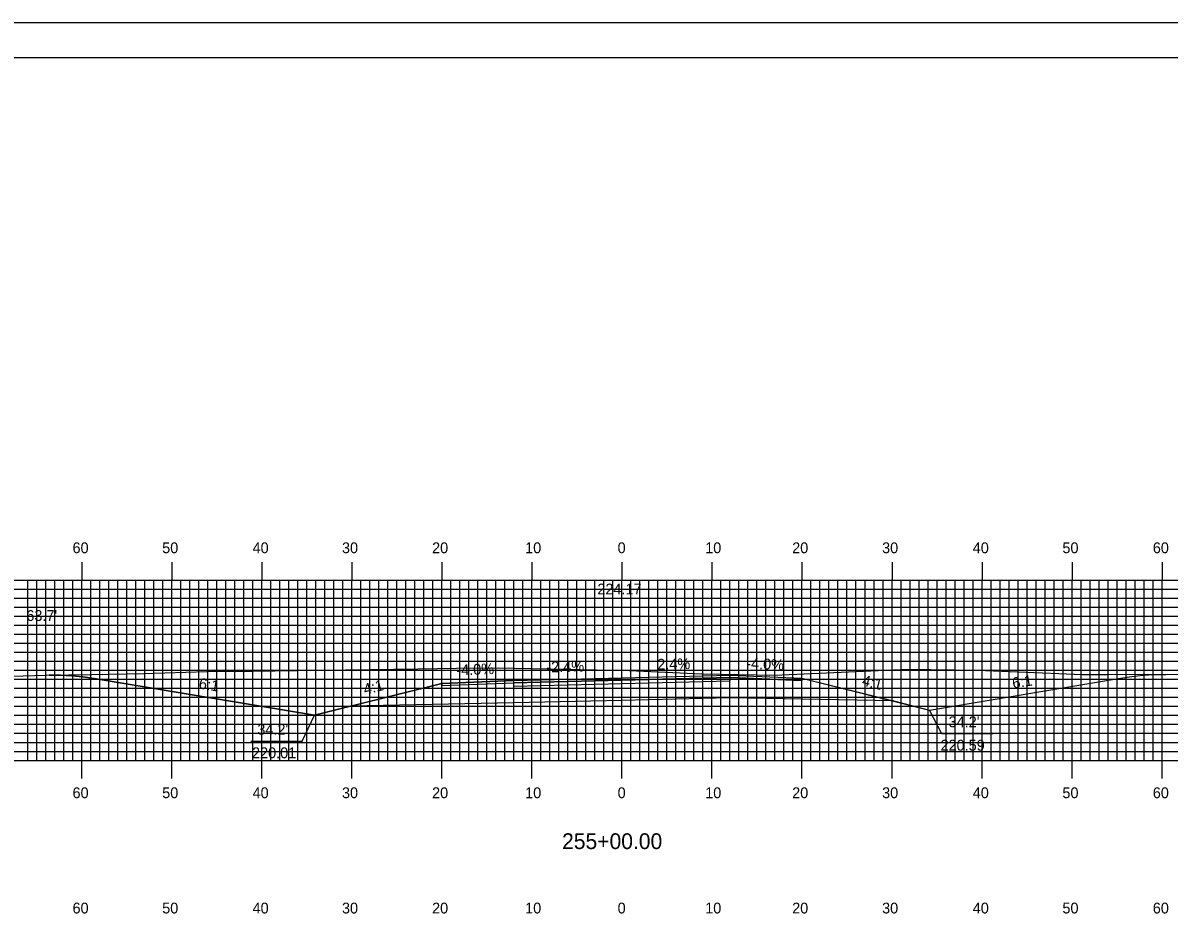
# Model space of a CAD drawing. Extents: x 1804684 to 1805027, y 442591 to 442811.
# Drawn here: x 1804783.1 to 1804910.5, y 442711.2 to 442810.5 of the extents above; entities that cross this region are included whole.
import ezdxf

# ---------------------------------------------------------------- set-up
doc = ezdxf.new("R2010")
doc.units = 0
for name, color, linetype in [('ANNOTATION', 7, 'Continuous'), ('BORDER', 7, 'Continuous'), ('D_Roadway_Centerline', 7, 'Continuous'), ('D_Roadway_Centerline_Text', 7, 'Continuous'), ('D_Roadway_Edge_Shoulder', 7, 'Continuous'), ('D_Roadway_Edge_TW', 7, 'Continuous'), ('D_Roadway_Pavement', 7, 'Continuous'), ('D_Roadway_SlopeLines', 7, 'Continuous'), ('D_Roadway_SubGrade', 7, 'Continuous'), ('D_Text_Standard', 7, 'Continuous'), ('H_V ANNOTATION', 7, 'Continuous'), ('MAJOR', 7, 'Continuous'), ('MINOR', 7, 'Continuous'), ('PLOT BOUNDARY', 7, 'Continuous'), ('S_Roadway_Centerline', 7, 'Continuous')]:
    doc.layers.add(name, color=color, linetype=linetype)

msp = doc.modelspace()

# ---------------------------------------------------------------- linework, layer by layer
at = {"layer": 'ANNOTATION'}
for points in [[(1804808.45, 442730.79), (1804814.14, 442730.79), (1804815.51, 442733.68)], [(1804890.92, 442731.62), (1804885.23, 442731.62), (1804883.85, 442734.26)]]:
    msp.add_lwpolyline(points, dxfattribs=at)
at = {"layer": 'BORDER'}
msp.add_lwpolyline([(1804700.08, 442596.67), (1805020.08, 442596.67), (1805020.08, 442806.67), (1804700.08, 442806.67)], close=True, dxfattribs=at)
at = {"layer": 'D_Roadway_Centerline'}
msp.add_lwpolyline([(1804786.06, 442738.13), (1804787.31, 442738.12), (1804788.56, 442738.06), (1804789.81, 442737.93), (1804791.06, 442737.75), (1804815.51, 442733.68), (1804819.51, 442734.68), (1804829.68, 442737.22), (1804837.68, 442737.54), (1804849.68, 442737.83), (1804861.68, 442738.12), (1804869.68, 442737.8), (1804879.85, 442735.26), (1804883.85, 442734.26), (1804905.08, 442737.79), (1804906.33, 442737.98), (1804907.58, 442738.11), (1804908.83, 442738.19), (1804910.08, 442738.22)], dxfattribs=at)
at = {"layer": 'D_Roadway_Edge_Shoulder'}
for points in [[(1804837.68, 442737.54), (1804829.68, 442737.22), (1804829.68, 442736.97), (1804837.68, 442737.29)], [(1804861.68, 442738.12), (1804869.68, 442737.8), (1804869.68, 442737.55), (1804861.68, 442737.87)]]:
    msp.add_lwpolyline(points, close=True, dxfattribs=at)
at = {"layer": 'D_Roadway_Edge_TW'}
msp.add_lwpolyline([(1804837.68, 442737.29), (1804837.68, 442737.54), (1804849.68, 442737.83), (1804861.68, 442738.12), (1804861.68, 442737.87), (1804849.68, 442737.58)], close=True, dxfattribs=at)
at = {"layer": 'D_Roadway_Pavement'}
msp.add_lwpolyline([(1804837.68, 442736.88), (1804837.68, 442737.29), (1804849.68, 442737.58), (1804861.68, 442737.87), (1804861.68, 442737.45), (1804849.68, 442737.16)], close=True, dxfattribs=at)
at = {"layer": 'D_Roadway_SlopeLines'}
for points in [[(1804815.51, 442733.68), (1804791.06, 442737.75), (1804789.81, 442737.93), (1804788.56, 442738.06), (1804787.31, 442738.12), (1804786.06, 442738.13)], [(1804829.68, 442737.22), (1804815.51, 442733.68)], [(1804869.68, 442737.8), (1804883.85, 442734.26)], [(1804883.85, 442734.26), (1804905.08, 442737.79), (1804906.33, 442737.98), (1804907.58, 442738.11), (1804908.83, 442738.19), (1804910.08, 442738.22)]]:
    msp.add_lwpolyline(points, dxfattribs=at)
at = {"layer": 'D_Roadway_SubGrade'}
msp.add_lwpolyline([(1804837.68, 442735.04), (1804819.51, 442734.68), (1804829.68, 442737.22), (1804829.68, 442736.97), (1804837.68, 442737.29), (1804849.68, 442737.58), (1804861.68, 442737.87), (1804869.68, 442737.55), (1804869.68, 442737.8), (1804879.85, 442735.26), (1804861.68, 442735.62), (1804849.68, 442735.33)], close=True, dxfattribs=at)
at = {"layer": 'MAJOR'}
for p, q in [((1804789.68, 442750.67), (1804789.68, 442748.67)), ((1804799.68, 442750.67), (1804799.68, 442748.67)), ((1804809.68, 442750.67), (1804809.68, 442748.67)), ((1804819.68, 442750.67), (1804819.68, 442748.67)), ((1804829.68, 442750.67), (1804829.68, 442748.67)), ((1804839.68, 442750.67), (1804839.68, 442748.67)), ((1804849.68, 442750.67), (1804849.68, 442748.67)), ((1804859.68, 442750.67), (1804859.68, 442748.67)), ((1804869.68, 442750.67), (1804869.68, 442748.67)), ((1804879.68, 442750.67), (1804879.68, 442748.67)), ((1804889.68, 442750.67), (1804889.68, 442748.67)), ((1804899.68, 442750.67), (1804899.68, 442748.67)), ((1804909.68, 442750.67), (1804909.68, 442748.67)), ((1804709.68, 442748.67), (1804989.68, 442748.67)), ((1804709.68, 442748.67), (1804989.68, 442748.67)), ((1804789.68, 442728.67), (1804789.68, 442748.67)), ((1804799.68, 442728.67), (1804799.68, 442748.67)), ((1804809.68, 442728.67), (1804809.68, 442748.67)), ((1804819.68, 442728.67), (1804819.68, 442748.67)), ((1804829.68, 442728.67), (1804829.68, 442748.67)), ((1804839.68, 442728.67), (1804839.68, 442748.67)), ((1804849.68, 442728.67), (1804849.68, 442748.67)), ((1804859.68, 442728.67), (1804859.68, 442748.67)), ((1804869.68, 442728.67), (1804869.68, 442748.67)), ((1804879.68, 442728.67), (1804879.68, 442748.67)), ((1804889.68, 442728.67), (1804889.68, 442748.67)), ((1804899.68, 442728.67), (1804899.68, 442748.67)), ((1804909.68, 442728.67), (1804909.68, 442748.67)), ((1804709.68, 442743.67), (1804989.68, 442743.67)), ((1804709.68, 442738.67), (1804989.68, 442738.67)), ((1804709.68, 442733.67), (1804989.68, 442733.67)), ((1804709.68, 442728.67), (1804989.68, 442728.67)), ((1804709.68, 442728.67), (1804989.68, 442728.67)), ((1804789.68, 442726.66), (1804789.68, 442728.67)), ((1804799.68, 442726.66), (1804799.68, 442728.67)), ((1804809.68, 442726.66), (1804809.68, 442728.67)), ((1804819.68, 442726.66), (1804819.68, 442728.67)), ((1804829.68, 442726.66), (1804829.68, 442728.67)), ((1804839.68, 442726.66), (1804839.68, 442728.67)), ((1804849.68, 442726.66), (1804849.68, 442728.67)), ((1804859.68, 442726.66), (1804859.68, 442728.67)), ((1804869.68, 442726.66), (1804869.68, 442728.67)), ((1804879.68, 442726.66), (1804879.68, 442728.67)), ((1804889.68, 442726.66), (1804889.68, 442728.67)), ((1804899.68, 442726.66), (1804899.68, 442728.67)), ((1804909.68, 442726.66), (1804909.68, 442728.67))]:
    msp.add_line(p, q, dxfattribs=at)
at = {"layer": 'MINOR'}
for p, q in [((1804783.68, 442728.67), (1804783.68, 442748.67)), ((1804784.68, 442728.67), (1804784.68, 442748.67)), ((1804785.68, 442728.67), (1804785.68, 442748.67)), ((1804786.68, 442728.67), (1804786.68, 442748.67)), ((1804787.68, 442728.67), (1804787.68, 442748.67)), ((1804788.68, 442728.67), (1804788.68, 442748.67)), ((1804790.68, 442728.67), (1804790.68, 442748.67)), ((1804791.68, 442728.67), (1804791.68, 442748.67)), ((1804792.68, 442728.67), (1804792.68, 442748.67)), ((1804793.68, 442728.67), (1804793.68, 442748.67)), ((1804794.68, 442728.67), (1804794.68, 442748.67)), ((1804795.68, 442728.67), (1804795.68, 442748.67)), ((1804796.68, 442728.67), (1804796.68, 442748.67)), ((1804797.68, 442728.67), (1804797.68, 442748.67)), ((1804798.68, 442728.67), (1804798.68, 442748.67)), ((1804800.68, 442728.67), (1804800.68, 442748.67)), ((1804801.68, 442728.67), (1804801.68, 442748.67)), ((1804802.68, 442728.67), (1804802.68, 442748.67)), ((1804803.68, 442728.67), (1804803.68, 442748.67)), ((1804804.68, 442728.67), (1804804.68, 442748.67)), ((1804805.68, 442728.67), (1804805.68, 442748.67)), ((1804806.68, 442728.67), (1804806.68, 442748.67)), ((1804807.68, 442728.67), (1804807.68, 442748.67)), ((1804808.68, 442728.67), (1804808.68, 442748.67)), ((1804810.68, 442728.67), (1804810.68, 442748.67)), ((1804811.68, 442728.67), (1804811.68, 442748.67)), ((1804812.68, 442728.67), (1804812.68, 442748.67)), ((1804813.68, 442728.67), (1804813.68, 442748.67)), ((1804814.68, 442728.67), (1804814.68, 442748.67)), ((1804815.68, 442728.67), (1804815.68, 442748.67)), ((1804816.68, 442728.67), (1804816.68, 442748.67)), ((1804817.68, 442728.67), (1804817.68, 442748.67)), ((1804818.68, 442728.67), (1804818.68, 442748.67)), ((1804820.68, 442728.67), (1804820.68, 442748.67)), ((1804821.68, 442728.67), (1804821.68, 442748.67)), ((1804822.68, 442728.67), (1804822.68, 442748.67)), ((1804823.68, 442728.67), (1804823.68, 442748.67)), ((1804824.68, 442728.67), (1804824.68, 442748.67)), ((1804825.68, 442728.67), (1804825.68, 442748.67)), ((1804826.68, 442728.67), (1804826.68, 442748.67)), ((1804827.68, 442728.67), (1804827.68, 442748.67)), ((1804828.68, 442728.67), (1804828.68, 442748.67)), ((1804830.68, 442728.67), (1804830.68, 442748.67)), ((1804831.68, 442728.67), (1804831.68, 442748.67)), ((1804832.68, 442728.67), (1804832.68, 442748.67)), ((1804833.68, 442728.67), (1804833.68, 442748.67)), ((1804834.68, 442728.67), (1804834.68, 442748.67)), ((1804835.68, 442728.67), (1804835.68, 442748.67)), ((1804836.68, 442728.67), (1804836.68, 442748.67)), ((1804837.68, 442728.67), (1804837.68, 442748.67)), ((1804838.68, 442728.67), (1804838.68, 442748.67)), ((1804840.68, 442728.67), (1804840.68, 442748.67)), ((1804841.68, 442728.67), (1804841.68, 442748.67)), ((1804842.68, 442728.67), (1804842.68, 442748.67)), ((1804843.68, 442728.67), (1804843.68, 442748.67)), ((1804844.68, 442728.67), (1804844.68, 442748.67)), ((1804845.68, 442728.67), (1804845.68, 442748.67)), ((1804846.68, 442728.67), (1804846.68, 442748.67)), ((1804847.68, 442728.67), (1804847.68, 442748.67)), ((1804848.68, 442728.67), (1804848.68, 442748.67)), ((1804850.68, 442728.67), (1804850.68, 442748.67)), ((1804851.68, 442728.67), (1804851.68, 442748.67)), ((1804852.68, 442728.67), (1804852.68, 442748.67)), ((1804853.68, 442728.67), (1804853.68, 442748.67)), ((1804854.68, 442728.67), (1804854.68, 442748.67)), ((1804855.68, 442728.67), (1804855.68, 442748.67)), ((1804856.68, 442728.67), (1804856.68, 442748.67)), ((1804857.68, 442728.67), (1804857.68, 442748.67)), ((1804858.68, 442728.67), (1804858.68, 442748.67)), ((1804860.68, 442728.67), (1804860.68, 442748.67)), ((1804861.68, 442728.67), (1804861.68, 442748.67)), ((1804862.68, 442728.67), (1804862.68, 442748.67)), ((1804863.68, 442728.67), (1804863.68, 442748.67)), ((1804864.68, 442728.67), (1804864.68, 442748.67)), ((1804865.68, 442728.67), (1804865.68, 442748.67)), ((1804866.68, 442728.67), (1804866.68, 442748.67)), ((1804867.68, 442728.67), (1804867.68, 442748.67)), ((1804868.68, 442728.67), (1804868.68, 442748.67)), ((1804870.68, 442728.67), (1804870.68, 442748.67)), ((1804871.68, 442728.67), (1804871.68, 442748.67)), ((1804872.68, 442728.67), (1804872.68, 442748.67)), ((1804873.68, 442728.67), (1804873.68, 442748.67)), ((1804874.68, 442728.67), (1804874.68, 442748.67)), ((1804875.68, 442728.67), (1804875.68, 442748.67)), ((1804876.68, 442728.67), (1804876.68, 442748.67)), ((1804877.68, 442728.67), (1804877.68, 442748.67)), ((1804878.68, 442728.67), (1804878.68, 442748.67)), ((1804880.68, 442728.67), (1804880.68, 442748.67)), ((1804881.68, 442728.67), (1804881.68, 442748.67)), ((1804882.68, 442728.67), (1804882.68, 442748.67)), ((1804883.68, 442728.67), (1804883.68, 442748.67)), ((1804884.68, 442728.67), (1804884.68, 442748.67)), ((1804885.68, 442728.67), (1804885.68, 442748.67)), ((1804886.68, 442728.67), (1804886.68, 442748.67)), ((1804887.68, 442728.67), (1804887.68, 442748.67)), ((1804888.68, 442728.67), (1804888.68, 442748.67)), ((1804890.68, 442728.67), (1804890.68, 442748.67)), ((1804891.68, 442728.67), (1804891.68, 442748.67)), ((1804892.68, 442728.67), (1804892.68, 442748.67)), ((1804893.68, 442728.67), (1804893.68, 442748.67)), ((1804894.68, 442728.67), (1804894.68, 442748.67)), ((1804895.68, 442728.67), (1804895.68, 442748.67)), ((1804896.68, 442728.67), (1804896.68, 442748.67)), ((1804897.68, 442728.67), (1804897.68, 442748.67)), ((1804898.68, 442728.67), (1804898.68, 442748.67)), ((1804900.68, 442728.67), (1804900.68, 442748.67)), ((1804901.68, 442728.67), (1804901.68, 442748.67)), ((1804902.68, 442728.67), (1804902.68, 442748.67)), ((1804903.68, 442728.67), (1804903.68, 442748.67)), ((1804904.68, 442728.67), (1804904.68, 442748.67)), ((1804905.68, 442728.67), (1804905.68, 442748.67)), ((1804906.68, 442728.67), (1804906.68, 442748.67)), ((1804907.68, 442728.67), (1804907.68, 442748.67)), ((1804908.68, 442728.67), (1804908.68, 442748.67)), ((1804709.68, 442747.67), (1804989.68, 442747.67)), ((1804709.68, 442746.67), (1804989.68, 442746.67)), ((1804709.68, 442745.67), (1804989.68, 442745.67)), ((1804709.68, 442744.67), (1804989.68, 442744.67)), ((1804709.68, 442742.67), (1804989.68, 442742.67)), ((1804709.68, 442741.67), (1804989.68, 442741.67)), ((1804709.68, 442740.67), (1804989.68, 442740.67)), ((1804709.68, 442739.67), (1804989.68, 442739.67)), ((1804709.68, 442737.67), (1804989.68, 442737.67)), ((1804709.68, 442736.67), (1804989.68, 442736.67)), ((1804709.68, 442735.67), (1804989.68, 442735.67)), ((1804709.68, 442734.67), (1804989.68, 442734.67)), ((1804709.68, 442732.67), (1804989.68, 442732.67)), ((1804709.68, 442731.67), (1804989.68, 442731.67)), ((1804709.68, 442730.67), (1804989.68, 442730.67)), ((1804709.68, 442729.67), (1804989.68, 442729.67))]:
    msp.add_line(p, q, dxfattribs=at)
at = {"layer": 'PLOT BOUNDARY'}
msp.add_lwpolyline([(1804683.89, 442590.55), (1805023.89, 442590.55), (1805023.89, 442810.55), (1804683.89, 442810.55)], close=True, dxfattribs=at)
at = {"layer": 'S_Roadway_Centerline'}
msp.add_lwpolyline([(1804779.35, 442737.94), (1804785.69, 442738.12), (1804790.81, 442738.21), (1804796.56, 442738.32), (1804803.56, 442738.54), (1804808.61, 442738.56), (1804813.65, 442738.64), (1804827.01, 442738.83), (1804831.32, 442738.9), (1804835.92, 442738.95), (1804850.47, 442738.64), (1804858.55, 442738.29), (1804866.64, 442738.12), (1804881.44, 442738.78), (1804889.14, 442738.68), (1804898.2, 442738.3), (1804900.81, 442738.21), (1804903.66, 442738.19), (1804913.35, 442738.24)], dxfattribs=at)

# ---------------------------------------------------------------- texts
at = {"layer": 'ANNOTATION'}
for s, rotation, p in [('-2.4%', 1.3748, (1804841.3, 442738.43)), ('2.4%', 1.3748, (1804853.62, 442738.73)), ('-4.0%', 357.7094, (1804863.47, 442738.85)), ('-4.0%', 2.2906, (1804831.31, 442738.09)), ('6:1', 350.5376, (1804802.62, 442736.66)), ('4:1', 14.0362, (1804821.13, 442735.95)), ('4:1', 345.9638, (1804876.27, 442737.01)), ('6:1', 9.4624, (1804893.14, 442736.63))]:
    msp.add_text(s, height=1.2, rotation=rotation, dxfattribs=at).set_placement(p)
for s, p in [("34.2'", (1804885.97, 442732.35)), ("34.2'", (1804809.18, 442731.51)), ('220.59', (1804885.07, 442729.75)), ('220.01', (1804808.59, 442728.91))]:
    msp.add_text(s, height=1.2, dxfattribs=at).set_placement(p)
at = {"layer": 'D_Roadway_Centerline'}
for s, p in [('C', (1804849.67, 442737.83)), ('L', (1804849.68, 442737.82))]:
    msp.add_text(s, height=0.0146, dxfattribs=at).set_placement(p)
at = {"layer": 'D_Roadway_Centerline_Text'}
msp.add_text('224.17', height=1.2, dxfattribs=at).set_placement((1804846.95, 442747.09))
at = {"layer": 'D_Text_Standard'}
msp.add_text("63.7'", height=1.2, dxfattribs=at).set_placement((1804783.52, 442744.15))
at = {"layer": 'H_V ANNOTATION'}
for s, height, p in [('60', 1.2, (1804788.65, 442751.67)), ('50', 1.2, (1804798.61, 442751.67)), ('40', 1.2, (1804808.65, 442751.67)), ('30', 1.2, (1804818.58, 442751.67)), ('20', 1.2, (1804828.59, 442751.67)), ('10', 1.2, (1804838.93, 442751.67)), ('0', 1.2, (1804849.2, 442751.67)), ('10', 1.2, (1804858.93, 442751.67)), ('20', 1.2, (1804868.59, 442751.67)), ('30', 1.2, (1804878.58, 442751.67)), ('40', 1.2, (1804888.65, 442751.67)), ('50', 1.2, (1804898.61, 442751.67)), ('60', 1.2, (1804908.65, 442751.67)), ('60', 1.2, (1804788.65, 442724.47)), ('50', 1.2, (1804798.61, 442724.47)), ('40', 1.2, (1804808.65, 442724.47)), ('30', 1.2, (1804818.58, 442724.47)), ('20', 1.2, (1804828.59, 442724.47)), ('10', 1.2, (1804838.93, 442724.47)), ('0', 1.2, (1804849.2, 442724.47)), ('10', 1.2, (1804858.93, 442724.47)), ('20', 1.2, (1804868.59, 442724.47)), ('30', 1.2, (1804878.58, 442724.47)), ('40', 1.2, (1804888.65, 442724.47)), ('50', 1.2, (1804898.61, 442724.47)), ('60', 1.2, (1804908.65, 442724.47)), ('255+00.00', 1.75, (1804843.03, 442718.82)), ('60', 1.2, (1804788.65, 442711.67)), ('50', 1.2, (1804798.61, 442711.67)), ('40', 1.2, (1804808.65, 442711.67)), ('30', 1.2, (1804818.58, 442711.67)), ('20', 1.2, (1804828.59, 442711.67)), ('10', 1.2, (1804838.93, 442711.67)), ('0', 1.2, (1804849.2, 442711.67)), ('10', 1.2, (1804858.93, 442711.67)), ('20', 1.2, (1804868.59, 442711.67)), ('30', 1.2, (1804878.58, 442711.67)), ('40', 1.2, (1804888.65, 442711.67)), ('50', 1.2, (1804898.61, 442711.67)), ('60', 1.2, (1804908.65, 442711.67))]:
    msp.add_text(s, height=height, dxfattribs=at).set_placement(p)

doc.saveas('drawing.dxf')
